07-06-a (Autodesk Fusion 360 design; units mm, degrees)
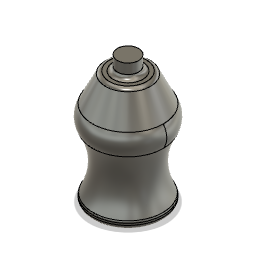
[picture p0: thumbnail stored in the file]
sketch "スケッチ1" plane through (0, 0, 0) normal (0, 1, 0) x axis (1, 0, 0)
  circle C1 centre (0, 0) radius 25
  point P1 (0, 0)
  point P2 (0, 0)
  coincident P1 P2
  dimension "d1" diameter C1 = 50
extrude "押し出し1" new body sketch "スケッチ1" along normal blind 5
work_plane "作業平面1" AlongDistance 20
sketch "スケッチ2" plane through (0, 25, 0) normal (0, 1, 0) x axis (1, 0, 0)
  circle C1 centre (0, 0) radius 20
  point P1 (0, 0)
  point P2 (0, 0)
  coincident P1 P2
  dimension "d5" diameter C1 = 40
work_plane "作業平面2" AlongDistance 20
sketch "スケッチ3" plane through (0, 45, 0) normal (0, 1, 0) x axis (1, 0, 0)
  circle C1 centre (0, 0) radius 25
loft "ロフト1" sketch "スケッチ2" + "スケッチ3"
work_plane "作業平面3" AlongDistance 15
sketch "スケッチ4" plane through (0, 60, 0) normal (0, 1, 0) x axis (1, 0, 0)
  circle C1 centre (0, 0) radius 25
sketch "スケッチ5" plane through (0, 0, 0) normal (0, 0, 1) x axis (1, 0, 0)
  line L1 (-25, 60) -> (25, 60)
  line L2 (25, 45) -> (-25, 45)
  arc A1 centre (-14.3816, 52.5) radius 13 clockwise from (-25, 45) to (-25, 60)
  arc A2 centre (14.3816, 52.5) radius 13 clockwise from (25, 60) to (25, 45)
  point P2 (-25, 60)
  point P9 (-25, 60)
  point P3 (-25, 45)
  point P10 (-25, 45)
  point P5 (25, 60)
  point P8 (25, 60)
  point P6 (25, 45)
  point P11 (25, 45)
  coincident P2 P9
  coincident P3 P10
  coincident P5 P8
  coincident P6 P11
  equal A1 A2
  dimension "d8" radius A1 = 13
sketch "スケッチ6" plane through (0, 0, 0) normal (1, 0, 0) x axis (0, 0, -1)
  line L1 (-25, 60) -> (25, 60)
  line L2 (25, 45) -> (-25, 45)
  arc A1 centre (-14.3816, 52.5) radius 13 clockwise from (-25, 45) to (-25, 60)
  arc A2 centre (14.3816, 52.5) radius 13 clockwise from (25, 60) to (25, 45)
  point P2 (-25, 60)
  point P9 (-25, 60)
  point P3 (-25, 45)
  point P10 (-25, 45)
  point P6 (25, 45)
  point P11 (25, 45)
  point P5 (25, 60)
  point P8 (25, 60)
  coincident P2 P9
  coincident P3 P10
  coincident P6 P11
  coincident P5 P8
  equal A1 A2
  dimension "d9" radius A1 = 13
loft "ロフト2" sketch "スケッチ4"
work_plane "作業平面4" AlongDistance 20
sketch "スケッチ7" plane through (0, 80, 0) normal (0, 1, 0) x axis (1, 0, 0)
  circle C1 centre (0, 0) radius 15
  point P1 (0, 0)
  point P2 (0, 0)
  coincident P1 P2
  dimension "d12" diameter C1 = 30
loft "ロフト3" sketch "スケッチ7"
sketch "スケッチ8" plane through (0, 80, 0) normal (0, 1, 0) x axis (-1, 0, 0)
  circle C1 centre (0, 0) radius 15
  circle C2 centre (0, 0) radius 7.5
  point P1 (0, 0)
  point P3 (0, 0)
  coincident P1 P3
  dimension "d13" diameter C2 = 15
extrude "押し出し2" add sketch "スケッチ8" profile of C2 along normal blind 10
fillet "フィレット" radius 3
